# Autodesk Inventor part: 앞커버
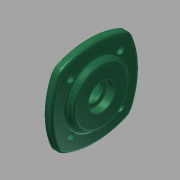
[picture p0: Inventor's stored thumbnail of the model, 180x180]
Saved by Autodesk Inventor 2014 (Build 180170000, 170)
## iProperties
Created: 2015-11
Part Number: 앞커버
Material: 일반
Document SubType Name: Modeling
Designer: mduedu
Density: 1 g/cm^3
Appearance: 매끄러움 - 짙은 바다 녹색
Mass: 112.858 g
Surface Area: 251.177 cm^2
Volume: 112.858 cm^3
Author: mduedu
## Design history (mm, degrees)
sketch "스케치1"
  geometry: L1 (50, 50)-(-50, 50); L2 (-50, 50)-(-50, -50); L3 (-50, -50)-(50, -50); L4 (50, -50)-(50, 50); L5 (0, 50)-(0, -50); L6 (50, 0)-(-50, 0); A1 r 90 centre (-40, 0) between (40.415, -40.415) and (40.415, 40.415); A2 r 90 centre (40, 0) between (-40.415, 40.415) and (-40.415, -40.415); A3 r 90 centre (0, -40) between (40.415, 40.415) and (-40.415, 40.415); A4 r 90 centre (0, 40) between (-40.415, -40.415) and (40.415, -40.415); 2 further points
  constraints: 12 end point, 8 point on circle, 5 midpoint, 4 centre point, 2 horizontal alignment, 2 parallel, 2 perpendicular, 2 symmetric about line, 2 tangent, 2 vertical alignment, 1 equal radius, 1 horizontal, 2 other
  dimensions: "d0" = 100 distance of L3.end L1.start; "d2" = 90 radius of A1
extrude "돌출1" new body sketch "스케치1" distance "d3" = 8; taper "d4" = 0 deg
sketch "스케치2"
  geometry: C1 r 35 at (0, 0); 1 further point
  constraints: 1 centre point, 1 coincident
  dimensions: "d5" = 70 diameter of C1
extrude "돌출2" join sketch "스케치2" distance "d6" = 7; taper "d7" = -30 deg
sketch "스케치3"
  geometry: L1 (0, 0)-(0, 40); L2 (0, 0)-(-28.284, 28.284); A1 r 40 centre (0, 0) between (0, 40) and (-28.284, 28.284); 2 further points
  constraints: 4 end point, 2 coincident, 2 point on circle, 1 centre point, 1 vertical
  dimensions: "d8" = 80 diameter of A1; "d9" = 45 deg angle of L1 L2
hole "구멍1" sketch "스케치3" at (-28.284, 28.284) diameter "d11" = 4.5; stored, may be unused: countersink angle "d15" = 90 deg, drill point angle "d17" = 118 deg; dims "d12" = 6, "d13" = 8, "d14" = 4.4, "d16" = 8
sketch "스케치4"
  geometry: C1 r 35 at (0, 0); 1 further point
  constraints: 1 centre point, 1 coincident
  dimensions: "d21" = 70 diameter of C1
extrude "돌출3" join sketch "스케치4" distance "d23" = 12; taper "d24" = 0 deg
hole "구멍2" diameter "d27" = 30; stored, may be unused: countersink angle "d31" = 90 deg, drill point angle "d33" = 0 deg; dims "d25" = 10, "d26" = 10, "d28" = 6, "d29" = 40, "d30" = 12, "d32" = 15
fillet "모깎기2" dims "d35" = 15
fillet "모깎기3" dims "d36" = 3
fillet "모깎기4" dims "d37" = 3
fillet "모깎기5" dims "d38" = 0.3
chamfer "모따기1" distance "d39" = 1; stored, may be unused: second distance "d40" = 2, angle "d41" = 45 deg
hole "구멍3" diameter "d44" = 20; stored, may be unused: countersink angle "d48" = 90 deg, drill point angle "d50" = 118 deg; dims "d45" = 6, "d46" = 30, "d47" = 8.7, "d49" = 8, "d55" = 10, "d56" = 10
fillet "모깎기6" dims "d51" = 0.3
chamfer "모따기2" distance "d52" = 0.7; stored, may be unused: second distance "d53" = 2, angle "d54" = 30 deg
node "솔리드1"
pattern_circular "원형 패턴1" dims angle "d19" = 360 deg
